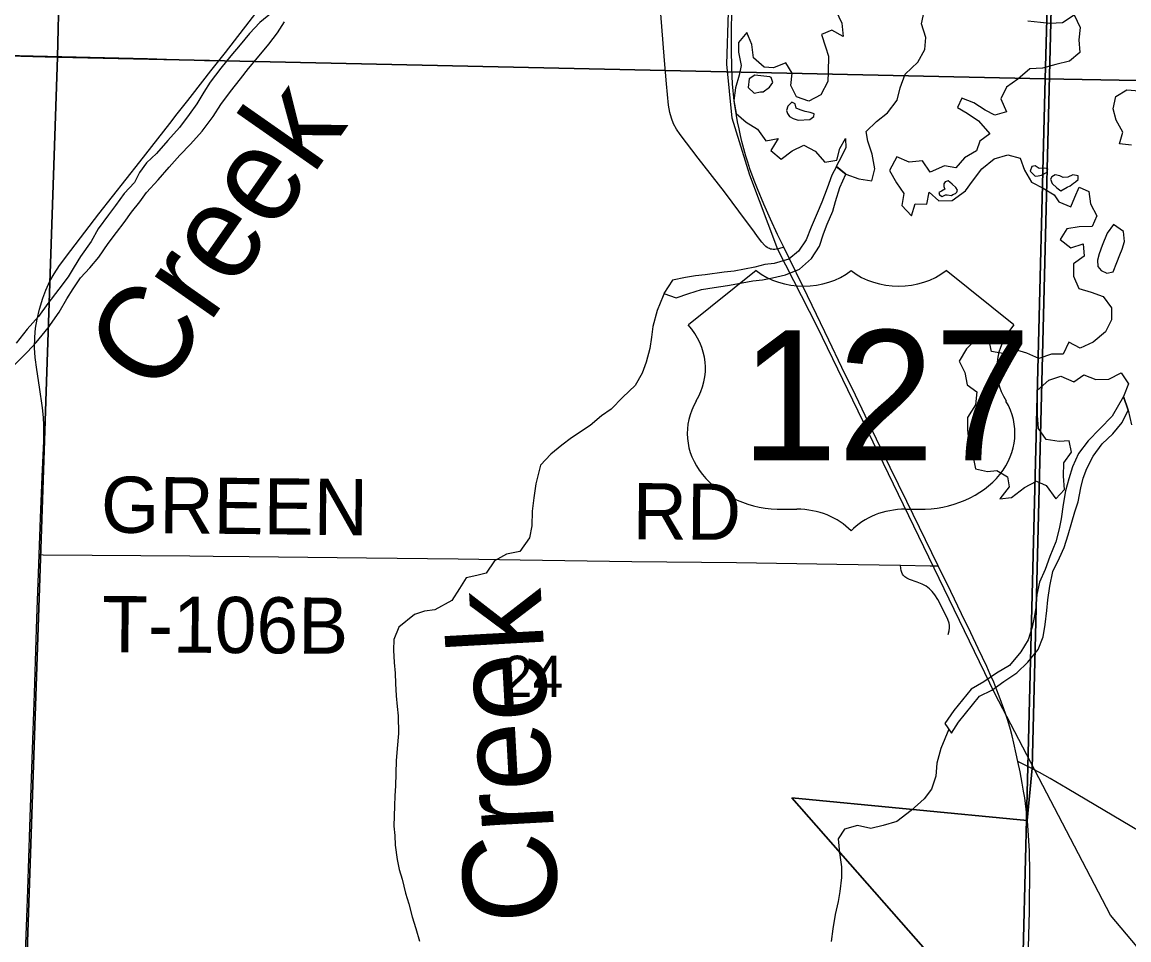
# Model space of a CAD drawing. Extents: x -38.1 to 35.9, y -2.7 to 28.5.
# Drawn here: x 20.979 to 22.099, y 17.155 to 18.084 of the extents above; entities that cross this region are included whole.
import ezdxf

# ---------------------------------------------------------------- set-up
doc = ezdxf.new("R2010")
doc.units = 0
for name, color, linetype in [('GM_P_County_Alignment', 7, 'Continuous'), ('GM_X_City_Street_Text', 7, 'Continuous'), ('GM_X_Corporation', 7, 'Continuous'), ('GM_X_Interchange_Ramps', 7, 'Continuous'), ('GM_X_Interstate_Location', 7, 'Continuous'), ('GM_X_Interstate_Shield', 7, 'Continuous'), ('GM_X_Major_River', 7, 'Continuous'), ('GM_X_Major_River_Text', 7, 'Continuous'), ('GM_X_Minor_Lake', 7, 'Continuous'), ('GM_X_Minor_River', 7, 'Continuous'), ('GM_X_Section', 7, 'Continuous'), ('GM_X_US_Location', 7, 'Continuous'), ('GM_X_US_Route', 7, 'Continuous')]:
    doc.layers.add(name, color=color, linetype=linetype)

msp = doc.modelspace()

# ---------------------------------------------------------------- linework, layer by layer
at = {"layer": 'GM_X_City_Street_Text'}
for points in [[(21.1781, 18.0447), (21.1847, 18.0529), (21.2178, 18.0958), (21.2376, 18.1213), (21.2615, 18.1522), (21.3101, 18.2144), (21.3532, 18.2691), (21.3954, 18.3228), (21.4206, 18.3552), (21.4457, 18.3876), (21.4565, 18.4012), (21.462, 18.4071), (21.4679, 18.4124), (21.4749, 18.4174), (21.4791, 18.42), (21.4828, 18.4223), (21.4871, 18.4246), (21.4915, 18.4269), (21.5217, 18.4412)], [(21.75, 17.8559), (21.7445, 17.8543), (21.7426, 17.8539), (21.7408, 17.8537), (21.7393, 17.8537), (21.7379, 17.8538), (21.7366, 17.8541), (21.7353, 17.8546), (21.7343, 17.8551), (21.7332, 17.8556), (21.7318, 17.8567), (21.7305, 17.8579), (21.7277, 17.8611), (21.7233, 17.8669), (21.7204, 17.871), (21.7175, 17.875), (21.7123, 17.882), (21.6898, 17.9119), (21.6631, 17.9461), (21.6451, 17.9699), (21.6412, 17.9755), (21.6383, 17.9808), (21.6361, 17.9865), (21.6344, 17.9924), (21.6332, 17.9996), (21.6311, 18.0212), (21.6293, 18.0448), (21.6264, 18.0794), (21.6226, 18.1259)], [(20.5142, 18.0615), (20.5304, 18.0611), (20.587, 18.0598), (20.6335, 18.0584), (20.6603, 18.058), (20.7504, 18.0558), (20.8497, 18.0534), (20.892, 18.0523), (20.9342, 18.0511), (20.9901, 18.0497), (21.1057, 18.0469), (21.1635, 18.0449), (21.1671, 18.0448), (21.1781, 18.0447)], [(20.9961, 17.5447), (20.9975, 17.5821), (20.9994, 17.6237), (21.0008, 17.6597), (21.0009, 17.6759), (21.0006, 17.6834), (20.9997, 17.6933), (20.9967, 17.7143), (20.9938, 17.7321), (20.9922, 17.7443), (20.9916, 17.7542), (20.9918, 17.7647), (20.9926, 17.7739), (20.9941, 17.783), (20.9966, 17.7932), (21, 17.8045), (21.003, 17.8126), (21.0071, 17.8215), (21.0113, 17.8291), (21.0168, 17.8373), (21.0282, 17.8527), (21.0567, 17.8897), (21.098, 17.9425), (21.1283, 17.9811), (21.136, 17.9909), (21.1414, 17.9977), (21.1468, 18.0045), (21.1514, 18.0104), (21.1699, 18.0345), (21.1781, 18.0447)], [(20.9799, 17.0408), (20.9807, 17.0766), (20.9822, 17.1325), (20.9836, 17.1772), (20.9846, 17.2058), (20.9868, 17.2691), (20.9897, 17.3573), (20.9914, 17.4045), (20.9939, 17.4802), (20.9954, 17.5256), (20.9961, 17.5447)]]:
    msp.add_lwpolyline(points, dxfattribs=at)
at = {"layer": 'GM_X_Corporation'}
msp.add_lwpolyline([(25.4101, 13.4873), (25.0847, 13.9186), (24.5478, 14.5412), (23.9622, 15.2897), (23.3945, 15.9977), (22.8429, 16.6968), (22.7771, 16.7664), (22.2793, 17.0387), (22.174, 17.095), (22.1183, 17.1348), (22.0806, 17.1798), (21.9636, 17.4041), (21.7841, 17.7749), (21.744, 17.8537), (21.7155, 17.9287), (21.6978, 17.9866), (21.6921, 18.0413), (21.6956, 18.1468), (21.7163, 18.7934), (21.7602, 19.7303), (21.7602, 19.7308)], dxfattribs=at)
at = {"layer": 'GM_X_Interchange_Ramps'}
for points in [[(21.75, 17.8559), (21.7436, 17.8688), (21.7363, 17.8842), (21.7297, 17.8994), (21.7232, 17.9149), (21.7205, 17.9219), (21.7179, 17.9288), (21.7155, 17.9354), (21.7134, 17.9421), (21.7116, 17.9482), (21.7095, 17.9556), (21.7076, 17.9629), (21.706, 17.9691), (21.7046, 17.9757), (21.7031, 17.9829), (21.7019, 17.9894), (21.7009, 17.9958), (21.7, 18.0015), (21.6994, 18.0076), (21.6986, 18.0144), (21.6981, 18.0212), (21.6972, 18.0367), (21.6969, 18.0567), (21.6969, 18.076), (21.6974, 18.0934)], [(21.9062, 17.5334), (21.8743, 17.5984), (21.8575, 17.633), (21.839, 17.6713), (21.8224, 17.706), (21.8087, 17.734), (21.7955, 17.7617), (21.7829, 17.7877), (21.7694, 17.8157), (21.7557, 17.8443), (21.75, 17.8559)], [(21.9867, 17.3354), (21.9852, 17.3431), (21.9828, 17.3537), (21.981, 17.3614), (21.9793, 17.3678), (21.9777, 17.3735), (21.9761, 17.3788), (21.9743, 17.3839), (21.9727, 17.3886), (21.9689, 17.3988), (21.9657, 17.4075), (21.9624, 17.4156), (21.9589, 17.4235), (21.9554, 17.4314), (21.9468, 17.4498), (21.9391, 17.4656), (21.9298, 17.4849), (21.919, 17.5073), (21.9062, 17.5334)], [(22.0008, 17.3283), (21.997, 17.3303), (21.9867, 17.3354)], [(22.1478, 17.242), (22.0368, 17.3081), (22.0196, 17.3182), (22.0087, 17.3242), (22.0016, 17.3279), (22.0008, 17.3283)]]:
    msp.add_lwpolyline(points, dxfattribs=at)
at = {"layer": 'GM_X_Interstate_Location'}
for p, q in [((21.7219, 17.8323), (21.6533, 17.7774)), ((21.9828, 17.7774), (21.9142, 17.8323)), ((21.7494, 17.5906), (21.7631, 17.5906)), ((21.873, 17.5906), (21.8867, 17.5906))]:
    msp.add_line(p, q, dxfattribs=at)
for centre, major_axis, start_param, end_param in [((21.77, 17.8715), (-0.0687, 0), 0.795399, 2.346194), ((21.8661, 17.8715), (-0.0687, 0), 0.795399, 2.346194), ((21.5745, 17.7333), (0.0961, 0), 5.838949, 6.894067), ((22.0616, 17.7333), (-0.0961, 0), 5.672304, 6.727422), ((21.7483, 17.6675), (0.0961, 0), 2.702327, 4.723529), ((21.8878, 17.6675), (-0.0961, 0), 1.559657, 3.580859), ((21.7631, 17.5357), (-0.0687, 0), 3.785094, 4.712389), ((21.873, 17.5357), (-0.0687, 0), 4.712389, 5.639684)]:
    msp.add_ellipse(centre, major_axis=major_axis, ratio=0.8, start_param=start_param, end_param=end_param, dxfattribs=at)
at = {"layer": 'GM_X_Interstate_Shield'}
for p, q in [((21.803, 17.9376), (21.8128, 17.9298)), ((22.0936, 17.7047), (22.0985, 17.6909))]:
    msp.add_line(p, q, dxfattribs=at)
for points in [[(21.8025, 18.0956), (21.8085, 18.0826), (21.81, 18.0692), (21.7984, 18.0756), (21.7881, 18.0714), (21.7922, 18.0587), (21.795, 18.0492), (21.7949, 18.0336), (21.7946, 18.0238), (21.7874, 18.0103), (21.7754, 18.0038), (21.7626, 18.008), (21.7569, 18.0195), (21.7584, 18.032), (21.7519, 18.0425), (21.7396, 18.0375), (21.7301, 18.0381), (21.7194, 18.0476), (21.7175, 18.0613), (21.7125, 18.0732), (21.7039, 18.0632), (21.704, 18.0533), (21.7066, 18.04), (21.7048, 18.0302), (21.701, 18.0174), (21.6995, 18.0045), (21.7017, 17.9912), (21.7117, 17.9825), (21.7233, 17.9753), (21.7317, 17.9637), (21.7443, 17.966), (21.7367, 17.9537), (21.7471, 17.9451), (21.7584, 17.9535), (21.7703, 17.9592), (21.7815, 17.9532), (21.7914, 17.9419), (21.8037, 17.9442), (21.8067, 17.9559), (21.8123, 17.9659)], [(21.8128, 17.9298), (21.8259, 17.9253), (21.8391, 17.923), (21.8421, 17.9351), (21.8392, 17.95), (21.835, 17.9634), (21.8334, 17.9729), (21.8436, 17.9833), (21.8548, 17.992), (21.8647, 18.0047), (21.8677, 18.0171), (21.8727, 18.031), (21.8856, 18.0431), (21.8928, 18.0562), (21.8936, 18.0683), (21.8894, 18.0821), (21.8921, 18.0946)], [(21.997, 18.0851), (22.0099, 18.0836), (22.0193, 18.0829), (22.0319, 18.0833), (22.0439, 18.0913), (22.05, 18.0783), (22.0485, 18.0658), (22.0496, 18.0529), (22.0391, 18.0444), (22.0253, 18.041), (22.0119, 18.0372), (21.999, 18.0365), (21.9869, 18.0262), (21.9753, 18.0178), (21.9696, 18.0062), (21.9753, 17.9931), (21.9634, 17.9897), (21.9537, 17.9945), (21.9421, 18.002), (21.9301, 18.0069), (21.9256, 17.9972), (21.9354, 17.9916), (21.9469, 17.9837), (21.9583, 17.9708), (21.9482, 17.9632), (21.9449, 17.9534), (21.9329, 17.9465), (21.9242, 17.9362), (21.9125, 17.9384), (21.8979, 17.932)], [(21.7359, 18.0285), (21.7268, 18.0295), (21.7207, 18.0301), (21.7149, 18.0264), (21.7139, 18.0177), (21.7198, 18.0119), (21.7263, 18.0132), (21.729, 18.0131)], [(21.729, 18.0131), (21.7356, 18.0179), (21.7388, 18.0227), (21.737, 18.0277), (21.7359, 18.0285)], [(22.1019, 17.9591), (22.0898, 17.9606), (22.0932, 17.9723), (22.0863, 17.9846), (22.0832, 17.9961), (22.0859, 18.0086), (22.0971, 18.0151), (22.11, 18.0143)], [(21.7766, 17.9924), (21.7717, 17.9933), (21.7664, 17.995), (21.7623, 17.9966), (21.7613, 18.0012), (21.7579, 18.0028), (21.754, 17.9987), (21.7527, 17.9942), (21.7538, 17.9912), (21.7556, 17.9881), (21.7593, 17.9861), (21.7646, 17.9844)], [(21.7646, 17.9844), (21.7764, 17.9852), (21.7803, 17.9881), (21.7807, 17.9908), (21.7766, 17.9924)], [(21.8123, 17.9659), (21.8128, 17.9564), (21.8055, 17.9426), (21.803, 17.9376)], [(21.8979, 17.932), (21.8902, 17.9432), (21.8769, 17.9421), (21.8642, 17.9474), (21.8569, 17.9335), (21.8641, 17.9212), (21.8714, 17.9103), (21.8695, 17.8983), (21.8791, 17.8877), (21.8829, 17.8998), (21.8946, 17.8994), (21.8969, 17.9115), (21.9069, 17.9029), (21.9202, 17.9033), (21.9338, 17.9131), (21.9409, 17.9228), (21.9504, 17.9354), (21.9629, 17.9453), (21.9766, 17.9494), (21.9891, 17.9461), (21.9937, 17.9338), (22.0005, 17.9218), (22.0125, 17.9158), (22.0237, 17.909)], [(22.0139, 17.9359), (22.0085, 17.9356), (22.0044, 17.9384), (22.001, 17.9377), (21.9993, 17.9329), (22.0045, 17.9278), (22.0075, 17.9281), (22.0106, 17.9287)], [(22.0106, 17.9287), (22.0164, 17.932), (22.0173, 17.9354), (22.0139, 17.9359)], [(22.0425, 17.9293), (22.0375, 17.9268), (22.0326, 17.9266), (22.0292, 17.9282), (22.0247, 17.9291), (22.0212, 17.9273), (22.02, 17.9247), (22.0217, 17.9204), (22.0262, 17.9161), (22.0303, 17.913), (22.0368, 17.9166), (22.0399, 17.918)], [(22.0399, 17.918), (22.043, 17.9206), (22.0453, 17.922), (22.0477, 17.9246), (22.0478, 17.9281), (22.0425, 17.9293)], [(21.9203, 17.9199), (21.9181, 17.9219), (21.9162, 17.9231), (21.9132, 17.922), (21.912, 17.9202), (21.9119, 17.9175), (21.913, 17.9148), (21.9095, 17.9127), (21.9068, 17.9112), (21.9075, 17.9089), (21.9101, 17.9073), (21.9135, 17.9088), (21.9154, 17.9091), (21.9196, 17.9082)], [(21.9196, 17.9082), (21.9211, 17.9093), (21.9238, 17.9104), (21.925, 17.9115), (21.9258, 17.9137), (21.924, 17.9164), (21.9203, 17.9199)], [(22.0237, 17.909), (22.0284, 17.902), (22.0404, 17.8968), (22.0445, 17.9065), (22.049, 17.9166), (22.0587, 17.9122), (22.0603, 17.9), (22.0667, 17.8877), (22.0622, 17.8768), (22.0489, 17.8764), (22.0363, 17.8745), (22.0296, 17.8637), (22.0403, 17.8554), (22.053, 17.8592), (22.0541, 17.847), (22.0433, 17.839), (22.0433, 17.8265), (22.0486, 17.8142), (22.061, 17.8104), (22.0731, 17.8059), (22.0815, 17.7946), (22.0815, 17.7825), (22.0754, 17.7702), (22.063, 17.7599), (22.0499, 17.7538), (22.0383, 17.7598), (22.0326, 17.7475), (22.0208, 17.7478), (22.0081, 17.7432), (21.9958, 17.7485), (21.9833, 17.7523), (21.9737, 17.748), (21.9601, 17.7503), (21.9574, 17.7629), (21.9457, 17.764), (21.9347, 17.7529), (21.9275, 17.7406), (21.9333, 17.7291), (21.9356, 17.7165), (21.9452, 17.7094), (21.9441, 17.6965), (21.9357, 17.6835), (21.9357, 17.6709), (21.9372, 17.6576), (21.9414, 17.645), (21.9441, 17.6316), (21.9561, 17.629), (21.9657, 17.6298), (21.9765, 17.6235), (21.9781, 17.6132), (21.9686, 17.6013), (21.9804, 17.6025), (21.9936, 17.6127), (22.0056, 17.6192), (22.0154, 17.6148), (22.0252, 17.6012), (22.0339, 17.6108), (22.0331, 17.6241), (22.0335, 17.6378), (22.041, 17.6486), (22.0387, 17.66), (22.0288, 17.6592), (22.0156, 17.6611), (22.0076, 17.6723), (22.0068, 17.6856), (22.0068, 17.6985), (22.0064, 17.711), (22.0181, 17.7213), (22.0304, 17.7255), (22.0435, 17.7198), (22.0536, 17.7268), (22.0656, 17.7219), (22.0789, 17.7222), (22.0913, 17.7287), (22.0989, 17.7175), (22.0936, 17.7047)], [(22.0836, 17.8788), (22.0772, 17.8703), (22.0723, 17.8575), (22.069, 17.8493), (22.0673, 17.8429), (22.0679, 17.8364), (22.0712, 17.8325), (22.0768, 17.8297), (22.0833, 17.831), (22.087, 17.8404), (22.0899, 17.8483)], [(22.0899, 17.8483), (22.0923, 17.8539), (22.0948, 17.8618), (22.0936, 17.8717), (22.0836, 17.8788)], [(22.0985, 17.6909), (22.1019, 17.676)]]:
    msp.add_lwpolyline(points, dxfattribs=at)
at = {"layer": 'GM_X_Major_River'}
for points in [[(21.75, 17.8559), (21.7436, 17.8688), (21.7363, 17.8842), (21.7297, 17.8994), (21.7232, 17.9149), (21.7205, 17.9219), (21.7179, 17.9288), (21.7155, 17.9354), (21.7134, 17.9421), (21.7116, 17.9482), (21.7095, 17.9556), (21.7076, 17.9629), (21.706, 17.9691), (21.7046, 17.9757), (21.7031, 17.9829), (21.7019, 17.9894), (21.7009, 17.9958), (21.7, 18.0015), (21.6994, 18.0076), (21.6986, 18.0144), (21.6981, 18.0212), (21.6972, 18.0367), (21.6969, 18.0567), (21.6969, 18.076), (21.6974, 18.0934)], [(21.9062, 17.5334), (21.8743, 17.5984), (21.8575, 17.633), (21.839, 17.6713), (21.8224, 17.706), (21.8087, 17.734), (21.7955, 17.7617), (21.7829, 17.7877), (21.7694, 17.8157), (21.7557, 17.8443), (21.75, 17.8559)], [(21.9867, 17.3354), (21.9852, 17.3431), (21.9828, 17.3537), (21.981, 17.3614), (21.9793, 17.3678), (21.9777, 17.3735), (21.9761, 17.3788), (21.9743, 17.3839), (21.9727, 17.3886), (21.9689, 17.3988), (21.9657, 17.4075), (21.9624, 17.4156), (21.9589, 17.4235), (21.9554, 17.4314), (21.9468, 17.4498), (21.9391, 17.4656), (21.9298, 17.4849), (21.919, 17.5073), (21.9062, 17.5334)], [(21.9965, 17.2751), (21.996, 17.2814), (21.9946, 17.2928), (21.9938, 17.2984), (21.9927, 17.3053), (21.9912, 17.3134), (21.989, 17.3248), (21.9867, 17.3354)], [(21.9986, 17.1897), (21.9989, 17.223), (21.9985, 17.2447), (21.9974, 17.2653), (21.9965, 17.2751)], [(21.9945, 17.0295), (21.9973, 17.1347), (21.9985, 17.1838), (21.9986, 17.1897)]]:
    msp.add_lwpolyline(points, dxfattribs=at)
at = {"layer": 'GM_X_Major_River_Text'}
for points in [[(20.9961, 17.5447), (21.0001, 17.5446), (21.1487, 17.5434), (21.1723, 17.5432), (21.2089, 17.5428), (21.3276, 17.5413), (21.4202, 17.5403), (21.4829, 17.5394), (21.596, 17.5379), (21.7022, 17.5368), (21.8035, 17.535), (21.8681, 17.534)], [(21.8681, 17.534), (21.8979, 17.5335), (21.9062, 17.5334)], [(21.9163, 17.4638), (21.9173, 17.4674), (21.9176, 17.4705), (21.9176, 17.4729), (21.9172, 17.4754), (21.9161, 17.4789), (21.9143, 17.4829), (21.9057, 17.4994), (21.9028, 17.5041), (21.9, 17.5075), (21.8974, 17.5101), (21.8939, 17.5127), (21.8901, 17.5148), (21.8849, 17.5169), (21.8773, 17.5195), (21.8745, 17.5208), (21.8725, 17.5222), (21.8712, 17.5235), (21.8701, 17.525), (21.8693, 17.5267), (21.8688, 17.5285), (21.8683, 17.5308), (21.8681, 17.534)]]:
    msp.add_lwpolyline(points, dxfattribs=at)
at = {"layer": 'GM_X_Section'}
for p, q in [((21.8128, 17.9298), (21.8031, 17.9376)), ((22.0985, 17.6909), (22.0936, 17.7047))]:
    msp.add_line(p, q, dxfattribs=at)
for points in [[(21.2323, 18.094), (21.2194, 18.0834), (21.2092, 18.0723), (21.1998, 18.0608), (21.1903, 18.0497), (21.1801, 18.0371), (21.1694, 18.023), (21.163, 18.0129), (21.1558, 18.001), (21.1479, 17.9902), (21.1384, 17.9772), (21.1266, 17.9639), (21.1149, 17.9509), (21.1047, 17.9414), (21.0976, 17.9317), (21.0927, 17.9216), (21.0821, 17.9102), (21.0734, 17.8983), (21.0663, 17.8886), (21.056, 17.8745), (21.0488, 17.8618), (21.0381, 17.8466), (21.0317, 17.8361), (21.0257, 17.8261), (21.0162, 17.8134), (21.0051, 17.799), (20.9956, 17.7859), (20.9839, 17.773), (20.9728, 17.7589)], [(20.971, 17.7366), (20.9839, 17.7495), (20.993, 17.7595), (21.0052, 17.7743), (21.0163, 17.7903), (21.0243, 17.8037), (21.0306, 17.8138), (21.0382, 17.8249), (21.0476, 17.8349), (21.0567, 17.846), (21.0662, 17.8598), (21.0745, 17.8709), (21.0824, 17.8809), (21.0895, 17.8914), (21.0982, 17.9017), (21.1049, 17.9114), (21.1167, 17.9243), (21.1277, 17.9369), (21.1387, 17.9491), (21.1493, 17.9602), (21.1611, 17.9735), (21.1722, 17.9884), (21.1801, 18.0003), (21.19, 18.0136), (21.1999, 18.0263), (21.2082, 18.037), (21.2172, 18.0478), (21.2287, 18.0615), (21.2374, 18.073), (21.2445, 18.0842)], [(21.8031, 17.9376), (21.7986, 17.9288), (21.7937, 17.9156), (21.7883, 17.9014), (21.7838, 17.8905), (21.7777, 17.8762), (21.7724, 17.8635), (21.7648, 17.8519), (21.7551, 17.8439), (21.7402, 17.8394), (21.7306, 17.8385), (21.7207, 17.8358), (21.71, 17.8338), (21.6997, 17.8318), (21.6894, 17.8306), (21.6703, 17.8281), (21.6604, 17.8269), (21.6505, 17.8253), (21.6371, 17.8226), (21.6284, 17.8092), (21.6408, 17.8047), (21.6538, 17.8092), (21.6665, 17.8131), (21.6794, 17.8153), (21.6928, 17.8172), (21.7023, 17.8188), (21.7184, 17.8218), (21.7283, 17.823), (21.7386, 17.825), (21.7516, 17.828), (21.7658, 17.8337), (21.7779, 17.8444), (21.7859, 17.857), (21.7901, 17.8694), (21.7938, 17.8792), (21.7995, 17.8923), (21.8024, 17.9021), (21.8066, 17.9164), (21.8128, 17.9298)], [(21.6287, 17.8091), (21.6279, 17.8066), (21.6218, 17.792), (21.6175, 17.7758), (21.616, 17.7648), (21.6142, 17.7535), (21.6107, 17.7395), (21.6066, 17.7283), (21.5994, 17.716), (21.5869, 17.7042), (21.5751, 17.692), (21.5654, 17.6851), (21.5538, 17.6755), (21.5351, 17.6628), (21.5251, 17.6555), (21.5141, 17.6463), (21.5036, 17.6353), (21.4988, 17.6164), (21.4969, 17.6021), (21.4953, 17.5888), (21.4949, 17.5737), (21.4926, 17.5616), (21.4827, 17.5478), (21.4694, 17.5452), (21.457, 17.5383), (21.4487, 17.526), (21.4391, 17.5237), (21.4284, 17.5213), (21.4216, 17.5105), (21.414, 17.4982), (21.3967, 17.4889), (21.3864, 17.4873), (21.376, 17.4841), (21.3601, 17.4713), (21.3551, 17.4589), (21.3548, 17.448), (21.3556, 17.4354), (21.3564, 17.4248), (21.3569, 17.4141)], [(22.0936, 17.7047), (22.0824, 17.6849), (22.0699, 17.672), (22.0581, 17.6598), (22.0482, 17.6472), (22.0421, 17.6337), (22.0383, 17.6213), (22.0349, 17.6093), (22.0326, 17.5953), (22.0307, 17.5809), (22.0285, 17.5707), (22.0251, 17.5576), (22.0193, 17.5429), (22.0144, 17.5298), (22.0086, 17.5167), (22.006, 17.5042), (22.0049, 17.491), (22.0034, 17.4811), (22.0012, 17.4713), (21.9971, 17.4586), (21.9899, 17.4462), (21.9784, 17.4325), (21.9653, 17.4246), (21.9525, 17.4158), (21.9397, 17.4086)], [(21.9479, 17.4015), (21.9606, 17.4076), (21.9726, 17.4164), (21.9858, 17.4251), (21.9968, 17.4358), (22.0074, 17.4488), (22.0123, 17.4615), (22.0146, 17.474), (22.0162, 17.488), (22.0172, 17.499), (22.0192, 17.5129), (22.0223, 17.5277), (22.0291, 17.5415), (22.0336, 17.552), (22.0378, 17.5648), (22.0416, 17.5776), (22.0446, 17.5881), (22.0479, 17.5983), (22.0506, 17.6122), (22.0528, 17.622), (22.0565, 17.6318), (22.063, 17.6445), (22.0721, 17.6568), (22.083, 17.6671), (22.0925, 17.6786), (22.0985, 17.6909)], [(21.3569, 17.4141), (21.3574, 17.4016), (21.3587, 17.3909), (21.3596, 17.3814), (21.36, 17.3636), (21.3585, 17.3484), (21.3574, 17.3359), (21.3569, 17.3105), (21.3563, 17.3006), (21.3557, 17.2904), (21.3552, 17.2699), (21.3561, 17.2604), (21.3567, 17.2505), (21.3586, 17.236), (21.3607, 17.2261), (21.3635, 17.2162), (21.367, 17.202), (21.3705, 17.1913), (21.3737, 17.178), (21.3776, 17.1661), (21.3811, 17.1535)], [(21.9397, 17.4086), (21.922, 17.3869), (21.913, 17.3738), (21.9196, 17.3638), (21.9267, 17.375), (21.9479, 17.4015)], [(21.9168, 17.368), (21.909, 17.3485), (21.9049, 17.3337), (21.9038, 17.3205), (21.8993, 17.3073), (21.8919, 17.2976), (21.8787, 17.2857), (21.8644, 17.2747), (21.8506, 17.2704), (21.838, 17.2673), (21.8244, 17.2706), (21.8114, 17.2667), (21.8051, 17.257), (21.8063, 17.2429), (21.8083, 17.2285), (21.8084, 17.2178), (21.8066, 17.2038), (21.8048, 17.1936), (21.8019, 17.1804), (21.7997, 17.166), (21.7979, 17.1532)]]:
    msp.add_lwpolyline(points, dxfattribs=at)
at = {"layer": 'GM_X_US_Route'}
for points in [[(20.0353, 19.0758), (21.0384, 19.0503), (21.0147, 18.0482), (20.0086, 18.0758)], [(21.0384, 19.0503), (22.0424, 19.0296), (22.0145, 18.0265), (21.0147, 18.0482)], [(23.1004, 19.0039), (23.0833, 18.0071), (22.0145, 18.0265), (22.0424, 19.0296)], [(21.0147, 18.0482), (20.9807, 17.043), (19.9831, 17.0625), (20.0086, 18.0758)], [(21.0147, 18.0482), (22.0145, 18.0265), (21.9892, 17.0222), (20.9807, 17.043)], [(23.0833, 18.0071), (23.083, 17.004), (21.9892, 17.0222), (22.0145, 18.0265)]]:
    msp.add_lwpolyline(points, close=True, dxfattribs=at)
for points in [[(21.9943, 17.03), (21.7582, 17.2984), (21.9963, 17.2757), (22.0014, 17.3284), (22.0312, 18.5289), (21.7139, 18.539), (21.6621, 18.5408), (20.0221, 18.5749), (20.0225, 18.5923), (20.0232, 18.6265), (20.0252, 18.6991)], [(25.4101, 18.4589), (22.0312, 18.5289), (22.0014, 17.3284), (21.9963, 17.2757), (21.7582, 17.2984), (21.9943, 17.03)]]:
    msp.add_lwpolyline(points, dxfattribs=at)

# ---------------------------------------------------------------- texts
at = {"layer": 'GM_P_County_Alignment'}
for s, p in [('0', (21.8181, 17.7059)), ('/', (21.8182, 17.7059))]:
    msp.add_text(s, height=0.000189, dxfattribs=at).set_placement(p)
msp.add_text('127', height=0.000189, rotation=0, dxfattribs=at).set_placement((21.7599, 17.6667))
at = {"layer": 'GM_X_Interstate_Location'}
msp.add_text('127', height=0.13184, dxfattribs=at).set_placement((21.7062, 17.64))
at = {"layer": 'GM_X_Minor_Lake'}
for s, rotation, p in [('GREEN', 359.3864, (21.0585, 17.5671)), ('RD', 359.5064, (21.5967, 17.5604)), ('T-106B', 359.5614, (21.0597, 17.4461))]:
    msp.add_text(s, height=0.05682, rotation=rotation, dxfattribs=at).set_placement(p)
at = {"layer": 'GM_X_Minor_River'}
msp.add_text('24', height=0.04186, rotation=0, dxfattribs=at).set_placement((21.4645, 17.4005))
at = {"layer": 'GM_X_US_Location'}
for height, rotation, p in [(0.09468, 55.0247, (21.1156, 17.7028)), (0.09466, 93.1529, (21.5224, 17.1741))]:
    msp.add_text('Creek', height=height, rotation=rotation, dxfattribs=at).set_placement(p)

doc.saveas('drawing.dxf')
